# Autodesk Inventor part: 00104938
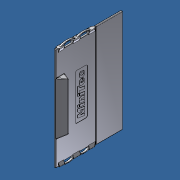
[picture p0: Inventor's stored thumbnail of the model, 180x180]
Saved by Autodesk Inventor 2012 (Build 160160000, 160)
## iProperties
Created: 2013-07
Part Number: 00104938
Material: Lexan, Clear
Document SubType Name: Modeling
Designer: Admin
Density: 1.2 g/cm^3
Mass: 21.7227 g
Surface Area: 194.137 cm^2
Volume: 18.1023 cm^3
Author: Admin
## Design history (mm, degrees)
node "001049381"
node "Volumenkörper1"
node "Base1"
